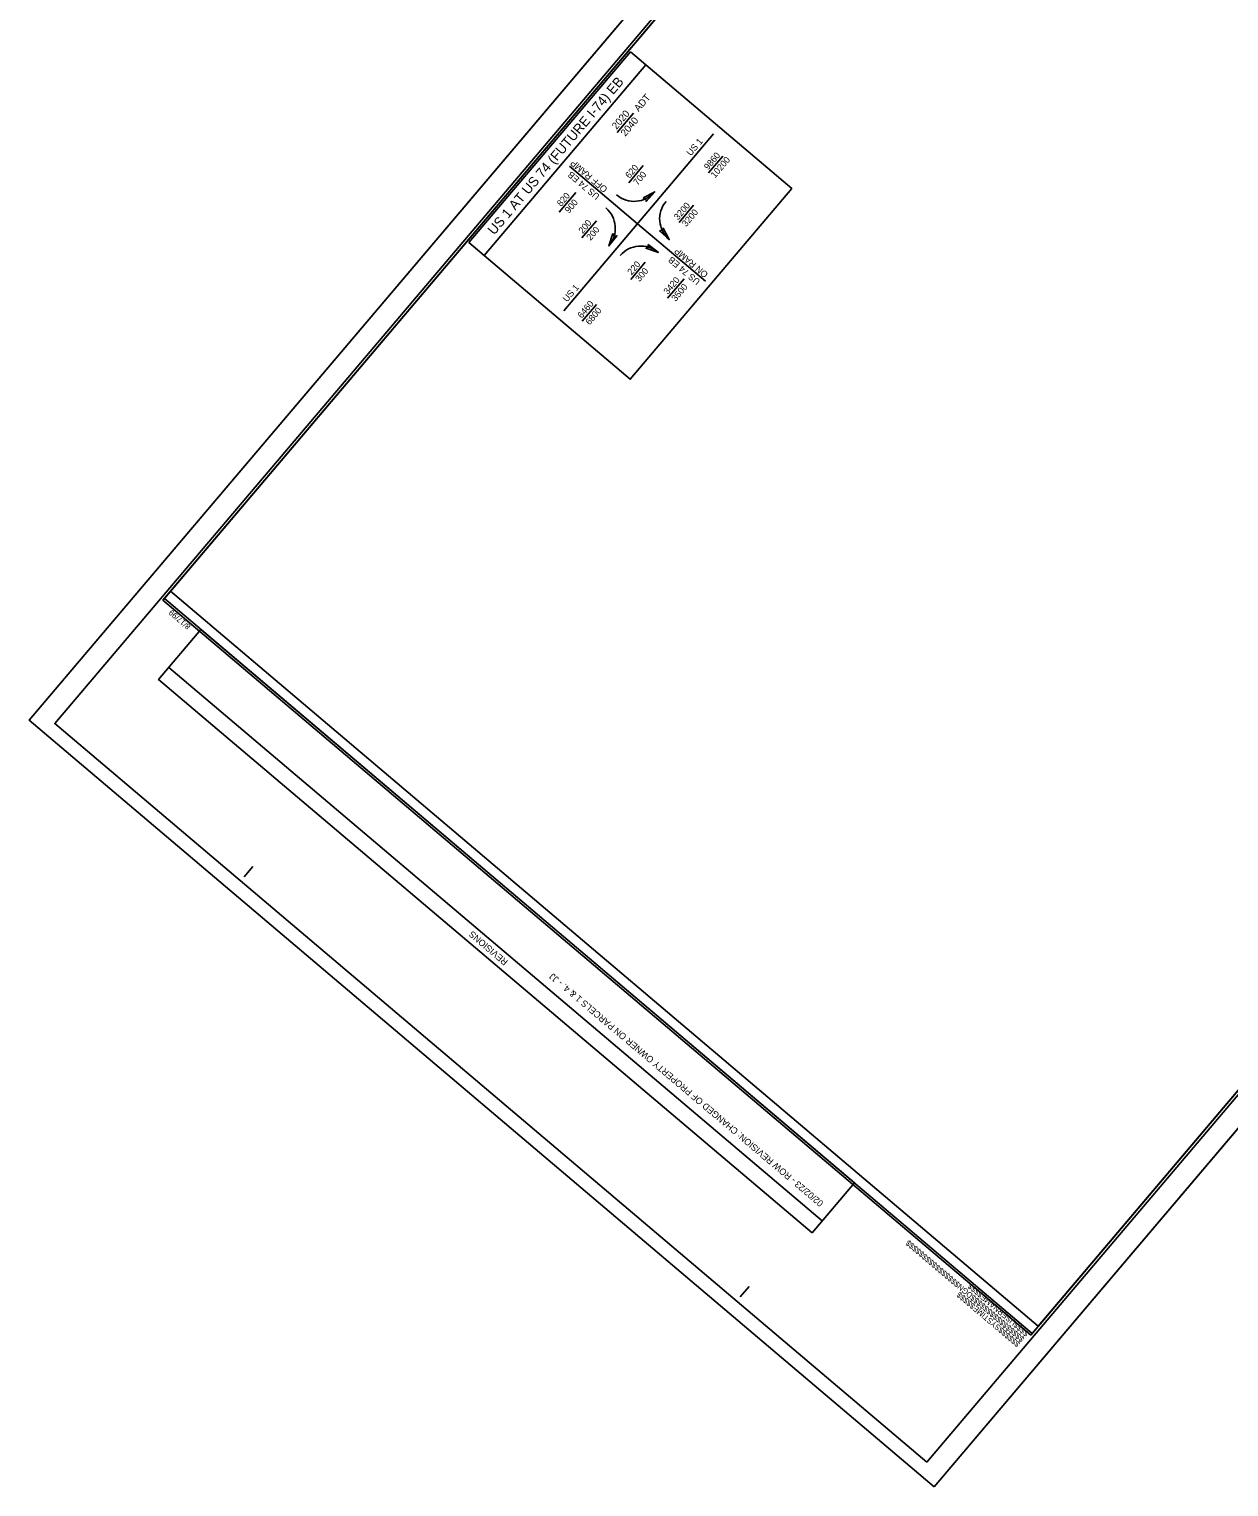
# Model space of a CAD drawing. Extents: x 1761000 to 1762924, y 421789 to 423893.
# Drawn here: x 1761000 to 1762108, y 421789 to 423135 of the extents above; entities that cross this region are included whole.
import ezdxf

# ---------------------------------------------------------------- set-up
doc = ezdxf.new("R2010")
doc.units = 0
for name, color, linetype in [('CTL Primary Horizontal and Vertical Cogo Number', 7, 'Continuous'), ('CTL Sheet Datum Description CELL', 7, 'Continuous'), ('Exist Other Culture Fence Line', 7, 'Continuous'), ('Exist Roads Change in Surface', 7, 'Continuous'), ('Exist Roads Change in Surface Text', 7, 'Continuous'), ('Exist Roads EOP Other', 7, 'Continuous'), ('Exist Roads EOT', 7, 'Continuous'), ('Exist Roads Soil', 7, 'Continuous'), ('Exist Roads Soil Text', 7, 'Continuous'), ('Exist Structure Major Deck Tunnel Box Culvert', 7, 'Continuous'), ('Exist Structure Major Deck Tunnel Box Culvert Text', 7, 'Continuous')]:
    doc.layers.add(name, color=color, linetype=linetype)

msp = doc.modelspace()

# ---------------------------------------------------------------- linework, layer by layer
at = {"layer": 'CTL Primary Horizontal and Vertical Cogo Number'}
msp.add_lwpolyline([(1761925, 421929.5), (1762829.9, 422997.7), (1762190.1, 423539.7), (1762067.8, 423395.3), (1761906.4, 423532), (1761123.8, 422608.2)], close=True, dxfattribs=at)
at = {"layer": 'CTL Sheet Datum Description CELL'}
msp.add_lwpolyline([(1761931.8, 421937.6), (1762821.5, 422987.8), (1762733.1, 423111.6), (1762720.6, 423144.4), (1762696.3, 423213.4), (1762251.7, 423590), (1762137.8, 423455.5), (1761965.3, 423601.6), (1761130.7, 422616.3)], close=True, dxfattribs=at)
at = {"layer": 'Exist Roads Change in Surface'}
msp.add_lwpolyline([(1761835.8, 421789.4), (1762924, 423073.9), (1762088.5, 423781.7), (1761000.3, 422497.2)], close=True, dxfattribs=at)
at = {"layer": 'Exist Roads Change in Surface Text'}
for p, q in [((1762088.5, 423781.7), (1761000.3, 422497.2)), ((1761835.8, 421789.4), (1762924, 423073.9)), ((1761000.3, 422497.2), (1761835.8, 421789.4))]:
    msp.add_line(p, q, dxfattribs=at)
at = {"layer": 'Exist Roads EOP Other'}
for p, q in [((1761125.1, 422609.7), (1761125.1, 422609.7)), ((1761198.9, 422352.5), (1761206.9, 422362.1)), ((1761656.7, 421964.7), (1761664.8, 421974.3)), ((1761926.2, 421931), (1761926.2, 421931))]:
    msp.add_line(p, q, dxfattribs=at)
for points in [[(1762094.7, 423754.2), (1761125.1, 422609.7), (1761926.2, 421931), (1762895.8, 423075.5)], [(1761926.2, 421931), (1761125.1, 422609.6), (1761965.3, 423601.6), (1762079.8, 423504.6), (1762209.1, 423657.2), (1762895.8, 423075.5)]]:
    msp.add_lwpolyline(points, close=True, dxfattribs=at)
at = {"layer": 'Exist Roads EOT'}
msp.add_line((1761732.4, 422034.9), (1761129.2, 422545.9), dxfattribs=at)
msp.add_lwpolyline([(1761723.1, 422023.8), (1761119.8, 422534.8), (1761158.9, 422581), (1761762.2, 422070)], close=True, dxfattribs=at)
at = {"layer": 'Exist Roads Soil'}
msp.add_lwpolyline([(1761828.9, 421812.2), (1762905.8, 423083.4), (1762100.8, 423765.4), (1761023.9, 422494.2)], close=True, dxfattribs=at)
at = {"layer": 'Exist Roads Soil Text'}
for points in [[(1761567.2, 422979.5), (1761577.8, 422985.2), (1761569.7, 422976.2), (1761569.6, 422978.8)], [(1761582.3, 422949.2), (1761591.1, 422941.1), (1761585.5, 422951.7), (1761584.8, 422949.3)], [(1761539.2, 422946.5), (1761535.4, 422935.2), (1761542.9, 422944.6), (1761540.3, 422944.3)], [(1761571.7, 422936.6), (1761581.1, 422929.2), (1761569.6, 422933), (1761572, 422934.1)]]:
    msp.add_lwpolyline(points, close=True, dxfattribs=at)
at = {"layer": 'Exist Structure Major Deck Tunnel Box Culvert'}
msp.add_lwpolyline([(1761125.1, 422609.6), (1761926.2, 421931), (1762895.8, 423075.5), (1762256, 423617.5), (1762101.4, 423434.9), (1761940, 423571.6)], close=True, dxfattribs=at)
at = {"layer": 'Exist Structure Major Deck Tunnel Box Culvert Text'}
for p, q in [((1761420.4, 422926.2), (1761569.6, 423102.3)), ((1761543.1, 423039.9), (1761558.2, 423057.8)), ((1761493.8, 422875.4), (1761632, 423038.6)), ((1761627.3, 423002.6), (1761640.6, 423018.2)), ((1761499.1, 423008.8), (1761561.8, 422955.7)), ((1761553.7, 422993.5), (1761567.2, 423009.3)), ((1761489.6, 422966.4), (1761504.9, 422984.4)), ((1761600.2, 422956.9), (1761613.6, 422972.8)), ((1761510.5, 422942.5), (1761524, 422958.3)), ((1761624.5, 422902.6), (1761561.8, 422955.7)), ((1761555.6, 422904.3), (1761569, 422920.1)), ((1761589.5, 422886.8), (1761604.8, 422904.9)), ((1761510.7, 422865.6), (1761523.9, 422881.2))]:
    msp.add_line(p, q, dxfattribs=at)
msp.add_lwpolyline([(1761406.3, 422938.2), (1761555.4, 423114.3), (1761704.3, 422988.2), (1761555.1, 422812.1)], close=True, dxfattribs=at)
for centre, start, end in [((1761558.7, 423001.3), 229.7301, 319.7301), ((1761607.3, 422960.1), 139.7301, 229.7301), ((1761516.3, 422951.3), 319.7301, 49.7301), ((1761564.9, 422910.1), 49.7301, 139.7301)]:
    msp.add_arc(centre, 25, start, end, dxfattribs=at)

# ---------------------------------------------------------------- texts
at = {"layer": 'Exist Other Culture Fence Line'}
for s, height, rotation, p in [('US 1 AT US 74 (FUTURE I-74) EB', 9, 49.7013, (1761429.5, 422944.7)), ('ADT', 6.56, 49.7013, (1761563, 423058.6)), ('2020', 6.56, 49.7013, (1761542.5, 423042.2)), ('2040', 6.56, 49.7013, (1761550.6, 423035.8)), ('US 1', 6, 49.7013, (1761611.1, 423017.8)), ('9860', 6, 49.7013, (1761627.1, 423004.9)), ('10200', 6, 49.7013, (1761633.4, 422997.4)), ('US 74 EB', 6, 139.7828, (1761527.5, 422981.8)), ('OFF RAMP', 6, 139.7828, (1761534.7, 422988.4)), ('620', 6, 49.7013, (1761554.5, 422997)), ('700', 6, 49.7013, (1761561.9, 422990.7)), ('820', 6, 49.7013, (1761491.4, 422971.1)), ('900', 6, 49.7013, (1761498.7, 422964.9)), ('3200', 6, 49.7013, (1761599.4, 422958.6)), ('3200', 6, 49.7013, (1761606.8, 422952.4)), ('200', 6, 49.7013, (1761511.3, 422946)), ('200', 6, 49.7013, (1761518.6, 422939.7)), ('US 74 EB', 6, 139.7828, (1761620.3, 422903.1)), ('ON RAMP', 6, 139.7828, (1761627.6, 422909.7)), ('220', 6, 49.7013, (1761556.4, 422907.8)), ('300', 6, 49.7013, (1761563.7, 422901.6)), ('US 1', 6, 49.7013, (1761496.8, 422882.9)), ('3420', 6, 49.7013, (1761589.8, 422889.8)), ('3500', 6, 49.7013, (1761597.1, 422883.5)), ('6460', 6, 49.7013, (1761510.4, 422867.9)), ('6800', 6, 49.7013, (1761517.7, 422861.7))]:
    msp.add_text(s, height=height, rotation=rotation, dxfattribs=at).set_placement(p)
at = {"layer": 'Exist Roads EOP Other'}
for s, p in [('8/17/99', (1761149.8, 422584.5)), ('$$$$$$$$$$$$$$$$DGN$$$$$$$$$$$$$$$$', (1761919.5, 421926.7)), ('$$$$$$SYSTIME$$$$$', (1761915.6, 421922)), ('$$$$USERNAME$$$$', (1761923.7, 421931.7))]:
    msp.add_text(s, height=5.25, rotation=139.7301, dxfattribs=at).set_placement(p)
at = {"layer": 'Exist Roads EOT'}
for s, p in [('REVISIONS', (1761442.8, 422274.9)), ('02/02/23 - ROW REVISION: CHANGED OF PROPERTY OWNER ON PARCELS 1 & 4. - JJ ', (1761734, 422052.1))]:
    msp.add_text(s, height=6, rotation=139.7301, dxfattribs=at).set_placement(p)

doc.saveas('drawing.dxf')
